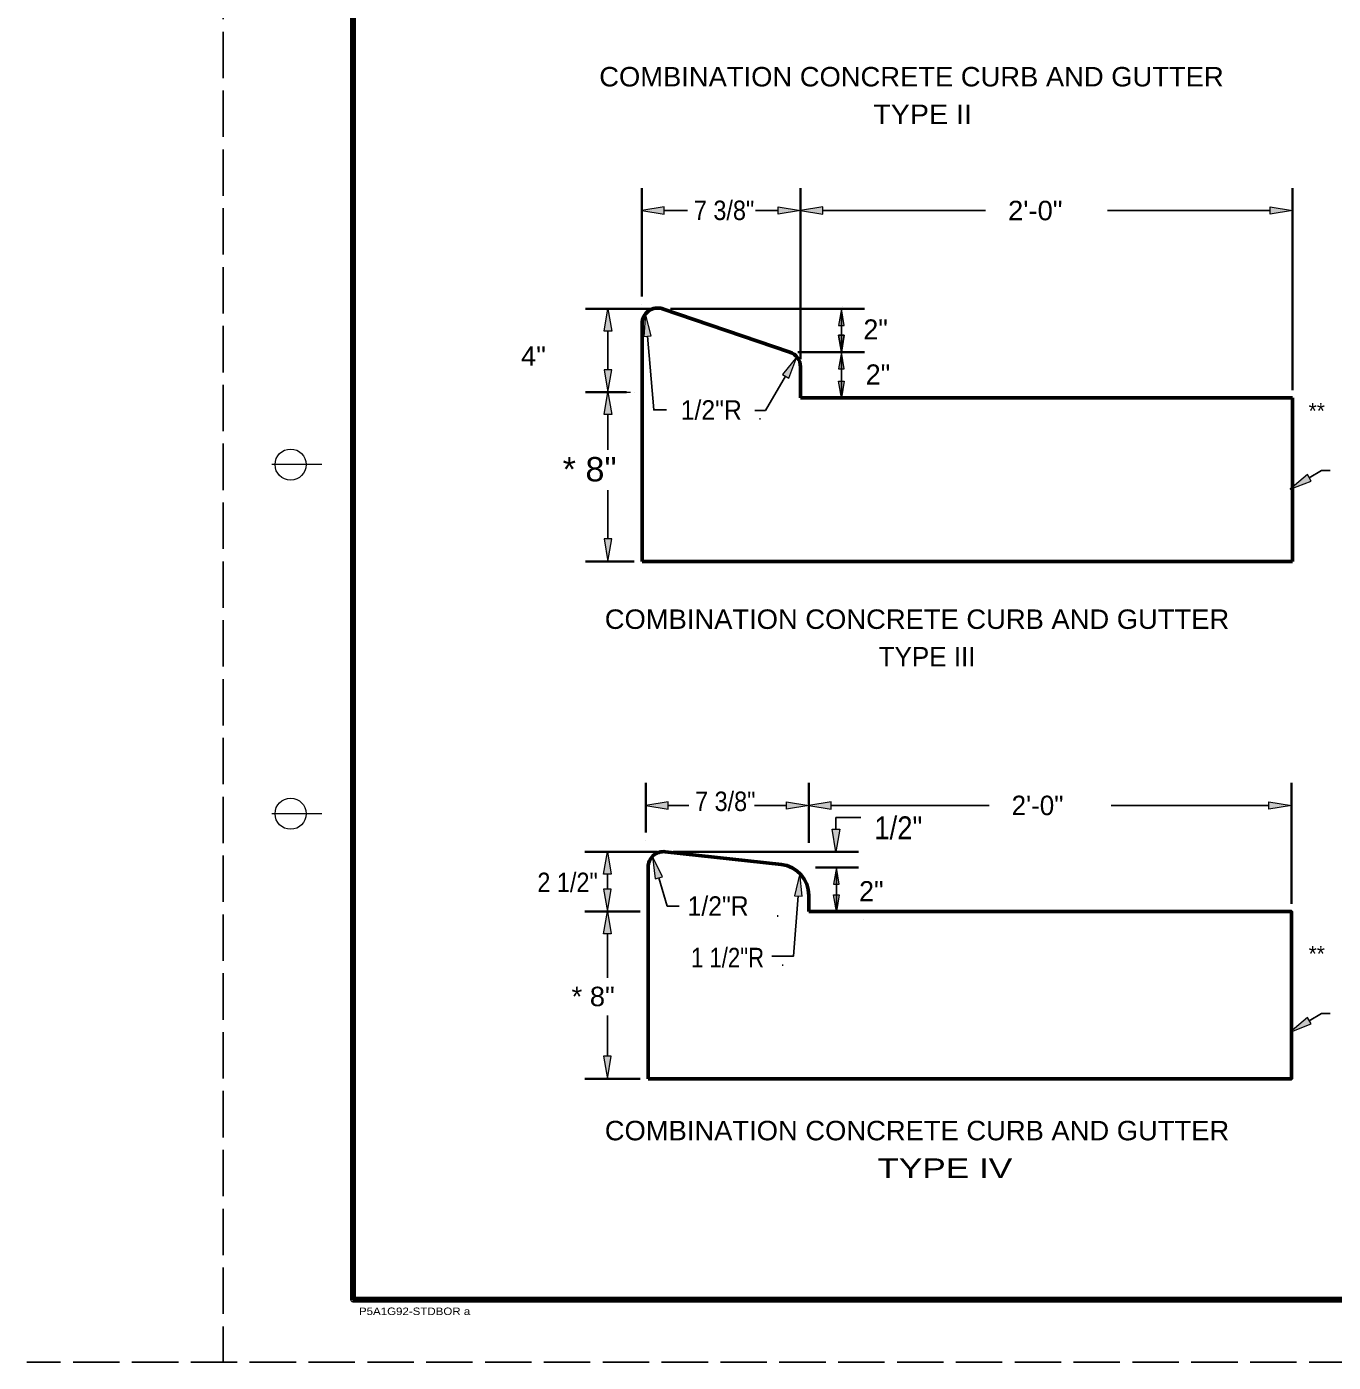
# Model space of a CAD drawing. Extents: x 36.6 to 71.9, y 0.8 to 22.8.
# Drawn here: x 36.59 to 47.06, y 0.78 to 11.49 of the extents above; entities that cross this region are included whole.
import ezdxf

# ---------------------------------------------------------------- set-up
doc = ezdxf.new("R2010")
doc.units = 0
doc.header["$LTSCALE"] = 0.062
doc.header["$PDMODE"] = 32
doc.header["$PDSIZE"] = 0.031
doc.linetypes.add('LONG_DASHED', pattern=[7.5, 6, -1.5])
for name, color, linetype, lineweight in [('1', 7, 'Continuous', 13), ('3', 7, 'Continuous', 25), ('8', 7, 'Continuous', 13)]:
    doc.layers.add(name, color=color, linetype=linetype, lineweight=lineweight)

msp = doc.modelspace()

# ---------------------------------------------------------------- hatches: boundary and pattern name
at = {"layer": '1'}
for points in [[(41.69883, 9.98633), (41.69883, 10.04633), (41.51883, 10.01633), (41.51883, 10.01633)], [(42.61092, 9.98633), (42.61092, 10.04633), (42.79092, 10.01633), (42.79092, 10.01633)], [(42.97083, 9.98633), (42.97083, 10.04633), (42.79092, 10.01633), (42.79092, 10.01633)], [(46.55817, 9.98633), (46.55817, 10.04633), (46.73817, 10.01633), (46.73817, 10.01633)], [(41.27725, 9.04783), (41.21725, 9.04783), (41.24725, 9.22792), (41.24725, 9.22792)], [(43.0965, 9.09292), (43.1415, 9.09292), (43.119, 9.22792), (43.119, 9.22792)], [(43.0965, 9.01625), (43.1415, 9.01625), (43.119, 8.88125), (43.119, 8.88125)], [(43.0965, 8.74625), (43.1415, 8.74625), (43.119, 8.88125), (43.119, 8.88125)], [(41.27725, 8.739), (41.21725, 8.739), (41.24725, 8.55892), (41.24725, 8.55892)], [(43.0965, 8.64875), (43.1415, 8.64875), (43.119, 8.51375), (43.119, 8.51375)], [(41.27717, 8.37908), (41.21725, 8.37908), (41.24725, 8.55908), (41.24725, 8.55908)], [(41.27717, 7.38233), (41.21725, 7.38233), (41.24725, 7.20233), (41.24725, 7.20233)], [(41.72967, 5.215), (41.72967, 5.27492), (41.54967, 5.245), (41.54967, 5.245)], [(42.6785, 5.215), (42.6785, 5.27492), (42.8585, 5.245), (42.8585, 5.245)], [(43.03842, 5.215), (43.03842, 5.27492), (42.8585, 5.245), (42.8585, 5.245)], [(46.54817, 5.215), (46.54817, 5.27492), (46.72817, 5.245), (46.72817, 5.245)], [(43.046, 5.05333), (43.106, 5.05333), (43.076, 4.87342), (43.076, 4.87342)], [(41.27258, 4.69342), (41.21258, 4.69342), (41.24267, 4.87342), (41.24267, 4.87342)], [(43.05667, 4.61242), (43.10167, 4.61242), (43.07917, 4.74742), (43.07917, 4.74742)], [(41.27258, 4.57358), (41.21258, 4.57358), (41.24267, 4.39367), (41.24267, 4.39367)], [(43.05667, 4.5285), (43.10167, 4.5285), (43.07917, 4.3935), (43.07917, 4.3935)], [(41.27258, 4.21367), (41.21258, 4.21367), (41.24267, 4.39367), (41.24267, 4.39367)], [(41.27258, 3.23275), (41.21258, 3.23275), (41.24267, 3.05275), (41.24267, 3.05275)]]:
    msp.add_hatch(color=256, dxfattribs=at).paths.add_polyline_path(points)
at = {"layer": '3'}
for points in [[(41.53383, 9.00583), (41.59358, 9.01092), (41.54817, 9.18775), (41.54817, 9.18775)], [(42.64583, 8.70183), (42.6975, 8.6715), (42.76283, 8.84192), (42.76283, 8.84192)], [(46.88733, 7.84692), (46.8565, 7.89842), (46.7175, 7.78033), (46.7175, 7.78033)], [(41.62683, 4.655), (41.68433, 4.67233), (41.60383, 4.83617), (41.60383, 4.83617)], [(42.74358, 4.52075), (42.80342, 4.51617), (42.78733, 4.69792), (42.78733, 4.69792)], [(46.88733, 3.49233), (46.8565, 3.54383), (46.7175, 3.42567), (46.7175, 3.42567)]]:
    msp.add_hatch(color=256, dxfattribs=at).paths.add_polyline_path(points)

# ---------------------------------------------------------------- linework, layer by layer
at = {"layer": '1', "linetype": 'LONG_DASHED', "lineweight": 25}
for p, q in [((38.16058, 22.77842), (38.16058, 0.77842)), ((71.78558, 0.77842), (36.58558, 0.77842))]:
    msp.add_line(p, q, dxfattribs=at)
at = {"layer": '1', "lineweight": 158}
msp.add_line((39.20225, 22.27842), (39.20225, 1.27842), dxfattribs=at)
at = {"layer": '1', "lineweight": 35}
for p, q in [((41.51883, 9.327), (41.51883, 10.19633)), ((42.79092, 8.82542), (42.79092, 10.19633)), ((46.73817, 8.57625), (46.73817, 10.19633)), ((41.62342, 9.22792), (41.06725, 9.22792)), ((41.68592, 9.22792), (42.70617, 8.88125)), ((41.74842, 9.22792), (43.30533, 9.22792)), ((42.76867, 8.88125), (43.30533, 8.88125)), ((42.79092, 8.76292), (42.79092, 8.51375)), ((41.39575, 8.55908), (41.06725, 8.55908)), ((41.45825, 7.20233), (41.06725, 7.20233)), ((41.54967, 5.02842), (41.54967, 5.425)), ((42.8585, 4.94567), (42.8585, 5.425)), ((46.72817, 4.456), (46.72817, 5.425)), ((41.64475, 4.87342), (41.06267, 4.87342)), ((41.76975, 4.87342), (43.256, 4.87342)), ((42.91183, 4.74742), (43.256, 4.74742)), ((41.50617, 4.39367), (41.06267, 4.39367)), ((41.50617, 3.05275), (41.06267, 3.05275))]:
    msp.add_line(p, q, dxfattribs=at)
at = {"layer": '1', "lineweight": 25}
for p, q in [((41.69883, 10.01633), (41.88433, 10.01633)), ((42.61092, 10.01633), (42.42975, 10.01633)), ((42.97092, 10.01633), (44.27583, 10.01633)), ((46.55817, 10.01633), (45.25333, 10.01633)), ((43.119, 9.06125), (43.119, 9.22792)), ((43.119, 8.88125), (43.119, 9.22792)), ((41.24725, 8.739), (41.24725, 9.04792)), ((43.119, 8.51375), (43.119, 8.88125)), ((41.24725, 8.37908), (41.24725, 8.09625)), ((41.24725, 7.77383), (41.24725, 7.38233)), ((41.72967, 5.245), (41.89633, 5.245)), ((42.6785, 5.245), (42.42158, 5.245)), ((43.0385, 5.245), (44.3045, 5.245)), ((43.076, 5.05342), (43.076, 5.14775)), ((46.54817, 5.245), (45.28208, 5.245)), ((41.24267, 4.69342), (41.24267, 4.57367)), ((43.07917, 4.3935), (43.07917, 4.69792)), ((41.24267, 3.86308), (41.24267, 4.21367)), ((41.24267, 3.23275), (41.24267, 3.55925))]:
    msp.add_line(p, q, dxfattribs=at)
at = {"layer": '1'}
for p, q in [((42.79092, 9.95383), (42.79092, 9.83633)), ((42.85342, 8.88125), (43.29492, 8.88125)), ((41.30975, 8.559), (41.42725, 8.559)), ((42.85342, 8.51375), (43.28025, 8.51375)), ((38.95225, 7.97842), (38.55225, 7.97842)), ((38.95225, 5.17842), (38.55225, 5.17842)), ((42.8585, 5.1825), (42.8585, 5.065)), ((41.30517, 4.39367), (41.42267, 4.39367)), ((42.921, 4.3935), (43.256, 4.3935))]:
    msp.add_line(p, q, dxfattribs=at)
at = {"layer": '1', "lineweight": 53}
for p, q in [((41.52075, 7.20233), (41.52075, 9.10958)), ((42.79092, 8.76292), (42.79092, 8.51375)), ((46.73817, 8.51375), (42.79092, 8.51375)), ((46.73817, 7.20233), (46.73817, 8.51375)), ((41.52075, 7.20233), (46.73817, 7.20233)), ((41.70725, 4.87342), (42.63917, 4.77142)), ((41.56867, 3.05275), (41.56867, 4.74917)), ((42.8585, 4.3935), (42.8585, 4.52333))]:
    msp.add_line(p, q, dxfattribs=at)
at = {"layer": '1', "lineweight": 158}
msp.add_lwpolyline([(71.70225, 22.27842), (71.70225, 1.27842), (39.20225, 1.27842)], dxfattribs=at)
at = {"layer": '1'}
for points in [[(41.69883, 9.98633), (41.69883, 10.04633), (41.51883, 10.01633), (41.51883, 10.01633)], [(42.61092, 9.98633), (42.61092, 10.04633), (42.79092, 10.01633), (42.79092, 10.01633)], [(42.97083, 9.98633), (42.97083, 10.04633), (42.79092, 10.01633), (42.79092, 10.01633)], [(46.55817, 9.98633), (46.55817, 10.04633), (46.73817, 10.01633), (46.73817, 10.01633)], [(41.27725, 9.04783), (41.21725, 9.04783), (41.24725, 9.22792), (41.24725, 9.22792)], [(43.0965, 9.09292), (43.1415, 9.09292), (43.119, 9.22792), (43.119, 9.22792)], [(43.0965, 8.74625), (43.1415, 8.74625), (43.119, 8.88125), (43.119, 8.88125)], [(41.27725, 8.739), (41.21725, 8.739), (41.24725, 8.55892), (41.24725, 8.55892)], [(43.0965, 8.64875), (43.1415, 8.64875), (43.119, 8.51375), (43.119, 8.51375)], [(41.27717, 8.37908), (41.21725, 8.37908), (41.24725, 8.55908), (41.24725, 8.55908)], [(41.27717, 7.38233), (41.21725, 7.38233), (41.24725, 7.20233), (41.24725, 7.20233)], [(41.72967, 5.215), (41.72967, 5.27492), (41.54967, 5.245), (41.54967, 5.245)], [(42.6785, 5.215), (42.6785, 5.27492), (42.8585, 5.245), (42.8585, 5.245)], [(43.03842, 5.215), (43.03842, 5.27492), (42.8585, 5.245), (42.8585, 5.245)], [(46.54817, 5.215), (46.54817, 5.27492), (46.72817, 5.245), (46.72817, 5.245)], [(43.046, 5.05333), (43.106, 5.05333), (43.076, 4.87342), (43.076, 4.87342)], [(41.27258, 4.69342), (41.21258, 4.69342), (41.24267, 4.87342), (41.24267, 4.87342)], [(43.05667, 4.61242), (43.10167, 4.61242), (43.07917, 4.74742), (43.07917, 4.74742)], [(41.27258, 4.57358), (41.21258, 4.57358), (41.24267, 4.39367), (41.24267, 4.39367)], [(43.05667, 4.5285), (43.10167, 4.5285), (43.07917, 4.3935), (43.07917, 4.3935)], [(41.27258, 4.21367), (41.21258, 4.21367), (41.24267, 4.39367), (41.24267, 4.39367)], [(41.27258, 3.23275), (41.21258, 3.23275), (41.24267, 3.05275), (41.24267, 3.05275)]]:
    msp.add_lwpolyline(points, close=True, dxfattribs=at)
at = {"layer": '1', "lineweight": 53}
for points in [[(41.68592, 9.22792), (42.70617, 8.88125), (42.70625, 8.88125)], [(41.56867, 3.05275), (46.72817, 3.05275), (46.72817, 4.3935), (42.8585, 4.3935)]]:
    msp.add_lwpolyline(points, dxfattribs=at)
at = {"layer": '1', "lineweight": 25}
msp.add_lwpolyline([(43.0965, 9.01625), (43.1415, 9.01625), (43.119, 8.88125), (43.119, 8.88125)], close=True, dxfattribs=at)
at = {"layer": '1'}
for centre in [(38.70225, 7.97842), (38.70225, 5.17842)]:
    msp.add_circle(centre, 0.125, dxfattribs=at)
at = {"layer": '1', "lineweight": 35}
for centre, start, end in [((41.64575, 9.10958), 71.23187, 180), ((42.66592, 8.76292), 0, 71.23187)]:
    msp.add_arc(centre, 0.125, start, end, dxfattribs=at)
at = {"layer": '1', "lineweight": 53}
for centre, radius, start, end in [((41.64575, 9.10958), 0.125, 71.23187, 180), ((42.66592, 8.76292), 0.125, 0, 71.23187), ((41.69367, 4.74917), 0.125, 83.75334, 180), ((42.6085, 4.52333), 0.25, 0, 83.75334)]:
    msp.add_arc(centre, radius, start, end, dxfattribs=at)
at = {"layer": '1'}
msp.add_point((39.20225, 1.27842), dxfattribs=at)
at = {"layer": '3'}
for p, q in [((43.076, 5.14775), (43.27508, 5.14775)), ((46.872, 3.51808), (46.97092, 3.57725)), ((46.97092, 3.57725), (47.03917, 3.57725))]:
    msp.add_line(p, q, dxfattribs=at)
at = {"layer": '3', "lineweight": 13}
for points in [[(41.53383, 9.00583), (41.59358, 9.01092), (41.54817, 9.18775), (41.54817, 9.18775)], [(42.64583, 8.70183), (42.6975, 8.6715), (42.76283, 8.84192), (42.76283, 8.84192)], [(46.88733, 7.84692), (46.8565, 7.89842), (46.7175, 7.78033), (46.7175, 7.78033)], [(41.62683, 4.655), (41.68433, 4.67233), (41.60383, 4.83617), (41.60383, 4.83617)], [(42.74358, 4.52075), (42.80342, 4.51617), (42.78733, 4.69792), (42.78733, 4.69792)], [(46.88733, 3.49233), (46.8565, 3.54383), (46.7175, 3.42567), (46.7175, 3.42567)]]:
    msp.add_lwpolyline(points, close=True, dxfattribs=at)
at = {"layer": '3'}
for points in [[(41.56367, 9.00842), (41.61483, 8.41692), (41.71608, 8.41692)], [(42.67175, 8.68667), (42.51042, 8.41158), (42.42508, 8.41158)], [(46.872, 7.87267), (46.97092, 7.93183), (47.03917, 7.93183)], [(41.65558, 4.66375), (41.72333, 4.43767), (41.81942, 4.43767)], [(42.7735, 4.5185), (42.73633, 4.03592), (42.56108, 4.03592)]]:
    msp.add_lwpolyline(points, dxfattribs=at)
at = {"layer": '8'}
for p, q in [((42.79092, 10.01633), (42.791, 10.01633)), ((42.79092, 10.01633), (42.791, 10.01633)), ((42.79092, 10.01633), (42.791, 10.01633)), ((41.24725, 9.22792), (41.24733, 9.22792)), ((41.51883, 9.2645), (41.51892, 9.2645)), ((41.68592, 9.22792), (41.686, 9.22792)), ((41.68592, 9.22792), (41.686, 9.22792)), ((43.12533, 9.24875), (43.12542, 9.24875)), ((43.12533, 9.22792), (43.12542, 9.22792)), ((42.79092, 8.88125), (42.791, 8.88125)), ((43.12533, 8.88125), (43.12542, 8.88125)), ((42.79092, 8.76292), (42.791, 8.76292)), ((41.24725, 8.559), (41.24733, 8.559)), ((41.45825, 8.55908), (41.45833, 8.55908)), ((42.79092, 8.51375), (42.791, 8.51375)), ((43.33683, 8.51375), (43.33692, 8.51375)), ((46.73817, 8.51375), (46.73825, 8.51375)), ((41.24725, 7.20233), (41.24733, 7.20233)), ((41.52075, 7.20233), (41.52083, 7.20233)), ((42.8585, 5.245), (42.85858, 5.245)), ((42.8585, 5.245), (42.85858, 5.245)), ((42.8585, 5.245), (42.85858, 5.245)), ((41.54967, 4.96592), (41.54975, 4.96592)), ((41.70725, 4.87342), (41.70733, 4.87342)), ((41.70725, 4.87342), (41.70733, 4.87342)), ((42.78733, 4.69792), (42.78742, 4.69792)), ((42.78733, 4.69792), (42.78742, 4.69792)), ((43.076, 4.69792), (43.07608, 4.69792)), ((43.0855, 4.69792), (43.08558, 4.69792)), ((42.8585, 4.52333), (42.85858, 4.52333)), ((41.24267, 4.39367), (41.24275, 4.39367)), ((41.24267, 4.39367), (41.24275, 4.39367)), ((41.24267, 4.39367), (41.24275, 4.39367)), ((41.56867, 4.39367), (41.56875, 4.39367)), ((42.8585, 4.3935), (42.85858, 4.3935)), ((46.72817, 4.3935), (46.72825, 4.3935)), ((43.297, 4.33042), (43.29708, 4.33042)), ((41.56867, 3.05275), (41.56875, 3.05275))]:
    msp.add_line(p, q, dxfattribs=at)

# ---------------------------------------------------------------- texts
at = {"layer": '1'}
for s, height, width, p in [('7 3/8"', 0.1562, 0.9, (41.93583, 9.93992)), ('2\'-0"', 0.1562, 1.05, (44.45583, 9.93825)), ('4"', 0.1562, 1.05, (40.54967, 8.77117)), ('* 8"', 0.1953, 1.05, (40.88367, 7.84375)), ('7 3/8"', 0.1562, 0.9, (41.94533, 5.19975)), ('1/2"', 0.1831, 0.9, (43.3835, 4.97383)), ('2 1/2"', 0.1562, 0.9, (40.68075, 4.5495)), ('* 8"', 0.1562, 1.05, (40.95542, 3.63442)), ('P5A1G92-STDBOR a', 0.06, 1.15, (39.25025, 1.15742))]:
    msp.add_text(s, height=height, dxfattribs=dict(at, width=width)).set_placement(p)
for s, height, p in [('2"', 0.1611, (43.29558, 8.982)), ('2"', 0.1611, (43.31458, 8.62092)), ('2\'-0"', 0.1562, (44.4845, 5.16692)), ('2"', 0.1611, (43.26133, 4.4765))]:
    msp.add_text(s, height=height, dxfattribs=at).set_placement(p)
at = {"layer": '3'}
for s, height, width, p in [('COMBINATION CONCRETE CURB AND GUTTER', 0.1562, 1.05, (41.17725, 11.01167)), ('TYPE II ', 0.1562, 1.1, (43.37492, 10.71025)), ('1/2"R', 0.1562, 0.95, (41.83092, 8.33867)), ('.', 0.09375, 0.9, (42.45058, 8.33775)), ('COMBINATION CONCRETE CURB AND GUTTER', 0.1562, 1.05, (41.22167, 6.66067)), ('1/2"R', 0.1562, 0.95, (41.88592, 4.35958)), ('.', 0.09375, 0.9, (42.59192, 4.35025)), ('1 1/2"R', 0.1562, 0.85, (41.913, 3.94658)), ('.', 0.09375, 0.9, (42.63333, 3.95633)), ('COMBINATION CONCRETE CURB AND GUTTER', 0.1562, 1.05, (41.22167, 2.55883)), ('TYPE IV ', 0.1562, 1.35, (43.40808, 2.25742))]:
    msp.add_text(s, height=height, dxfattribs=dict(at, width=width)).set_placement(p)
for s, height, p in [('**', 0.125, (46.86667, 8.34733)), ('TYPE III', 0.1562, (43.41767, 6.35933)), ('**', 0.125, (46.86667, 3.99275))]:
    msp.add_text(s, height=height, dxfattribs=at).set_placement(p)

doc.saveas('drawing.dxf')
